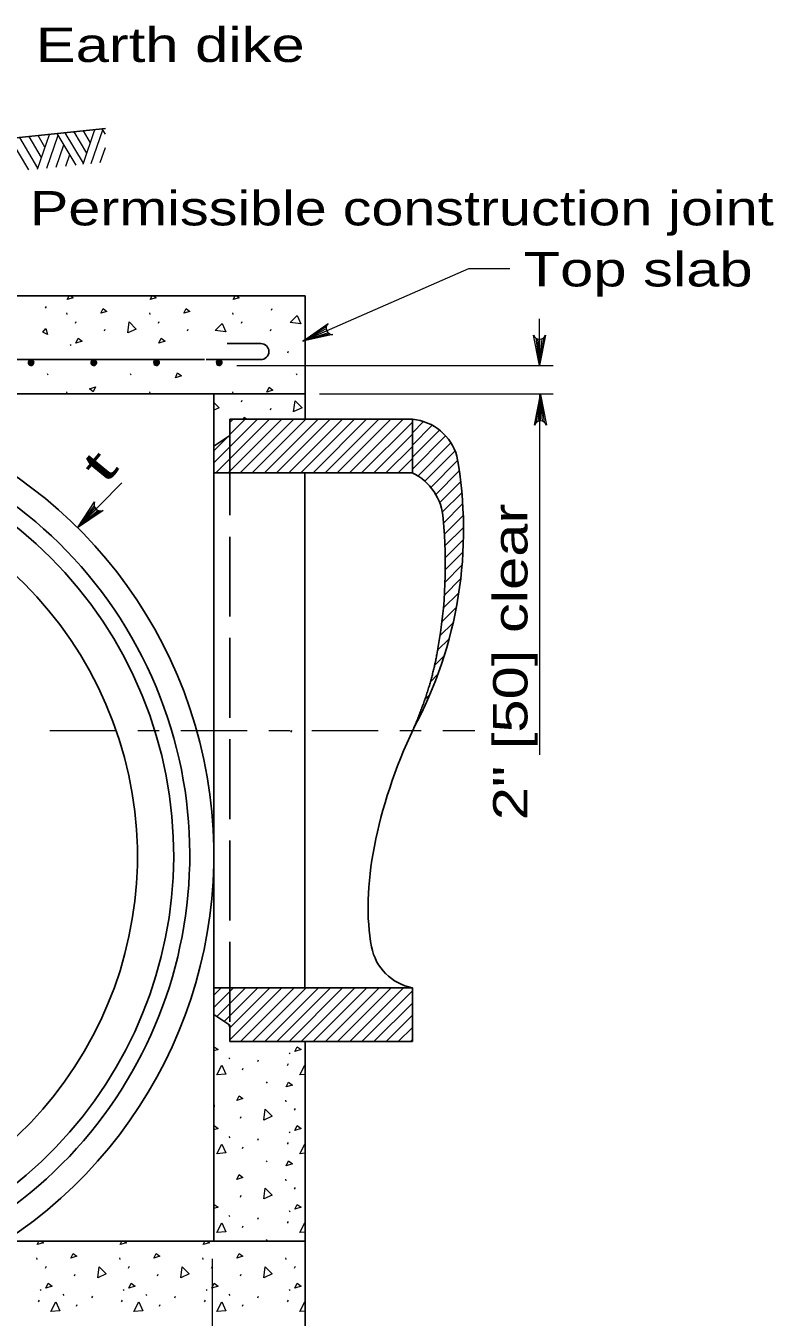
# Model space of a CAD drawing. Extents: x 1073.4 to 1107.4, y 719.4 to 741.4.
# Drawn here: x 1091.11 to 1094.59, y 723.69 to 729.71 of the extents above; entities that cross this region are included whole.
import ezdxf
from ezdxf.enums import TextEntityAlignment as Align

# ---------------------------------------------------------------- set-up
doc = ezdxf.new("R2010")
doc.units = 0
doc.header["$LTSCALE"] = 0.062
doc.linetypes.add('DOT_DASHED', pattern=[7.7, 5, -1.2, 0.3, -1.2])
doc.linetypes.add('LONG_DASHED', pattern=[7.5, 6, -1.5])
doc.layers.add('1', color=7, linetype='Continuous', lineweight=13)

msp = doc.modelspace()

# ---------------------------------------------------------------- linework, layer by layer
at = {"layer": '1', "lineweight": 25}
for p, q in [((1089.772, 729.04842), (1091.48392, 729.22825)), ((1088.59667, 728.44875), (1092.41392, 728.44875)), ((1092.41392, 728.44875), (1092.41392, 727.87408)), ((1092.20792, 728.22683), (1092.05158, 728.22683)), ((1088.59667, 728.15183), (1091.94608, 728.15183)), ((1091.95383, 728.15183), (1092.20792, 728.15183)), ((1092.41392, 727.99275), (1088.59667, 727.99275)), ((1091.98908, 724.04508), (1091.98908, 727.99275)), ((1092.41392, 727.87408), (1092.91367, 727.87408)), ((1092.91367, 727.62417), (1092.91367, 727.87408)), ((1092.91367, 727.62417), (1091.98908, 727.62417)), ((1092.41317, 727.62417), (1092.41317, 725.22558)), ((1092.41392, 724.97575), (1092.41392, 723.54533)), ((1087.26608, 724.04508), (1092.41392, 724.04508))]:
    msp.add_line(p, q, dxfattribs=at)
at = {"layer": '1'}
for p, q in [((1091.12817, 729.03533), (1091.04033, 729.18167)), ((1091.16992, 729.04408), (1091.08475, 729.18642)), ((1091.18675, 729.09408), (1091.12925, 729.19108)), ((1091.16833, 729.0395), (1091.22325, 729.20075)), ((1091.20208, 729.14117), (1091.17025, 729.19533)), ((1091.21092, 729.04408), (1091.26333, 729.19742)), ((1091.34758, 729.05842), (1091.25925, 729.20467)), ((1091.38183, 729.06683), (1091.29692, 729.20858)), ((1091.39783, 729.11342), (1091.33858, 729.213)), ((1091.37992, 729.06175), (1091.435, 729.22358)), ((1091.41442, 729.162), (1091.3815, 729.21742)), ((1091.41825, 729.06583), (1091.47133, 729.22208)), ((1091.48392, 729.20242), (1091.46942, 729.22675)), ((1091.25475, 729.04867), (1091.29017, 729.15325)), ((1091.46025, 729.07025), (1091.48392, 729.14075)), ((1091.29975, 729.05333), (1091.31767, 729.10742)), ((1091.20575, 728.392), (1091.20925, 728.4)), ((1091.30625, 728.43142), (1091.31458, 728.44875)), ((1091.69283, 728.43142), (1091.70117, 728.44875)), ((1092.07942, 728.43142), (1092.08775, 728.44875)), ((1092.1685, 728.44875), (1092.16633, 728.44833)), ((1092.16792, 728.44858), (1092.16675, 728.44875)), ((1091.30283, 728.36942), (1091.30367, 728.36142)), ((1091.68933, 728.36942), (1091.69025, 728.36142)), ((1092.07592, 728.36942), (1092.07683, 728.36142)), ((1092.257, 728.38175), (1092.26058, 728.38975)), ((1093.50608, 728.12433), (1093.50608, 728.34175)), ((1091.34492, 728.32225), (1091.3485, 728.33025)), ((1091.47983, 728.28575), (1091.48342, 728.29375)), ((1091.7315, 728.32225), (1091.73508, 728.33025)), ((1091.86642, 728.28575), (1091.86992, 728.29375)), ((1092.11808, 728.32225), (1092.12158, 728.33025)), ((1092.25292, 728.28575), (1092.25658, 728.29375)), ((1092.51308, 728.30525), (1092.40292, 728.23742)), ((1092.51267, 728.29542), (1092.40292, 728.23742)), ((1092.51508, 728.28658), (1092.40292, 728.23742)), ((1091.31925, 728.22283), (1091.32275, 728.2175)), ((1092.52175, 728.27692), (1092.40292, 728.23742)), ((1092.52958, 728.27133), (1092.40292, 728.23742)), ((1093.48817, 728.2525), (1093.50608, 728.12433)), ((1093.497, 728.24817), (1093.50608, 728.12433)), ((1093.52592, 728.254), (1093.50608, 728.12433)), ((1093.51758, 728.24908), (1093.50608, 728.12433)), ((1093.50608, 728.24683), (1093.50608, 728.12433)), ((1092.33383, 728.18283), (1092.33733, 728.19083)), ((1092.09675, 728.12433), (1093.569, 728.12433)), ((1091.21308, 728.08708), (1091.21658, 728.08175)), ((1091.59967, 728.08708), (1091.60325, 728.08175)), ((1092.37283, 728.08708), (1092.37633, 728.08175)), ((1091.30283, 728.00208), (1091.30367, 727.99408)), ((1091.68933, 728.00208), (1091.69025, 727.99408)), ((1092.07592, 728.00208), (1092.07683, 727.99408)), ((1092.48058, 727.99275), (1093.569, 727.99275)), ((1093.491, 727.859), (1093.51083, 727.98875)), ((1093.49925, 727.86392), (1093.51083, 727.98875)), ((1093.50608, 727.99275), (1093.50608, 726.31108)), ((1093.51083, 727.86617), (1093.51083, 727.98875)), ((1093.51992, 727.86483), (1093.51083, 727.98875)), ((1093.52875, 727.8605), (1093.51083, 727.98875)), ((1092.11808, 727.95492), (1092.12158, 727.96292)), ((1092.25292, 727.9185), (1092.25658, 727.92642)), ((1091.98908, 727.67108), (1092.19208, 727.87408)), ((1091.99875, 727.62417), (1092.24858, 727.87408)), ((1092.05533, 727.62417), (1092.30525, 727.87408)), ((1092.06408, 727.86875), (1092.06933, 727.87408)), ((1092.06408, 727.85908), (1092.07892, 727.87408)), ((1092.06408, 727.80258), (1092.13558, 727.87408)), ((1092.11183, 727.62417), (1092.36167, 727.87408)), ((1092.16842, 727.62417), (1092.41825, 727.87408)), ((1092.22492, 727.62417), (1092.47483, 727.87408)), ((1092.2815, 727.62417), (1092.53133, 727.87408)), ((1092.338, 727.62417), (1092.58792, 727.87408)), ((1092.39458, 727.62417), (1092.64442, 727.87408)), ((1092.45108, 727.62417), (1092.70092, 727.87408)), ((1092.50758, 727.62417), (1092.75758, 727.87408)), ((1092.56417, 727.62417), (1092.814, 727.87408)), ((1092.62075, 727.62417), (1092.87058, 727.87408)), ((1092.67725, 727.62417), (1092.91367, 727.86058)), ((1092.91367, 727.87408), (1092.91492, 727.87408)), ((1092.91367, 727.86708), (1092.91983, 727.87333)), ((1092.91367, 727.8105), (1092.96625, 727.86317)), ((1092.73383, 727.62417), (1092.91367, 727.80408)), ((1092.91367, 727.754), (1093.00558, 727.846)), ((1092.91367, 727.69742), (1093.03992, 727.82375)), ((1091.98908, 727.72758), (1092.05367, 727.79217)), ((1092.79025, 727.62417), (1092.91367, 727.7475)), ((1092.91367, 727.64092), (1093.06892, 727.79617)), ((1092.93892, 727.60975), (1093.09342, 727.76417)), ((1092.84692, 727.62417), (1092.91367, 727.69092)), ((1092.97158, 727.58575), (1093.1125, 727.72667)), ((1092.99925, 727.55683), (1093.12458, 727.68225)), ((1093.02258, 727.52367), (1093.13225, 727.63342)), ((1091.56083, 727.5775), (1091.35433, 727.36875)), ((1093.04075, 727.48533), (1093.13858, 727.58308)), ((1093.05325, 727.44125), (1093.14408, 727.53208)), ((1091.43175, 727.4725), (1091.35433, 727.36875)), ((1091.43492, 727.46317), (1091.35433, 727.36875)), ((1091.4405, 727.45583), (1091.35433, 727.36875)), ((1091.45025, 727.44942), (1091.35433, 727.36875)), ((1091.45958, 727.447), (1091.35433, 727.36875)), ((1093.05875, 727.39033), (1093.14808, 727.4795)), ((1093.0625, 727.3375), (1093.15058, 727.4255)), ((1093.06525, 727.28375), (1093.15183, 727.37017)), ((1093.067, 727.22892), (1093.15158, 727.31342)), ((1093.06683, 727.17217), (1093.14908, 727.25442)), ((1093.06542, 727.11433), (1093.14483, 727.19367)), ((1093.06275, 727.05508), (1093.13858, 727.13092)), ((1093.05775, 726.99358), (1093.13008, 727.06583)), ((1093.051, 726.93017), (1093.11858, 726.99783)), ((1093.04225, 726.865), (1093.10375, 726.92642)), ((1093.03158, 726.79767), (1093.08517, 726.85133)), ((1093.01725, 726.72683), (1093.06192, 726.77158)), ((1092.99783, 726.65083), (1093.03283, 726.68592)), ((1092.97208, 726.56867), (1092.99525, 726.59175)), ((1092.93825, 726.47825), (1092.94683, 726.48683)), ((1092.34733, 726.41708), (1092.35375, 726.42342)), ((1091.98908, 725.19092), (1092.02375, 725.22558)), ((1091.98908, 725.13442), (1092.08025, 725.22558)), ((1092.00275, 725.0915), (1092.13683, 725.22558)), ((1092.03667, 725.06892), (1092.19342, 725.22558)), ((1092.06408, 725.03975), (1092.24992, 725.22558)), ((1092.06408, 724.98317), (1092.3065, 725.22558)), ((1092.11308, 724.97575), (1092.36292, 725.22558)), ((1092.16967, 724.97575), (1092.41958, 725.22558)), ((1092.22617, 724.97575), (1092.47608, 725.22558)), ((1092.28275, 724.97575), (1092.53258, 725.22558)), ((1092.33925, 724.97575), (1092.58917, 725.22558)), ((1092.39583, 724.97575), (1092.64567, 725.22558)), ((1092.45233, 724.97575), (1092.70225, 725.22558)), ((1092.50892, 724.97575), (1092.75883, 725.22558)), ((1092.56542, 724.97575), (1092.81525, 725.22558)), ((1092.622, 724.97575), (1092.87192, 725.22558)), ((1092.6785, 724.97575), (1092.91367, 725.21083)), ((1092.73508, 724.97575), (1092.91367, 725.15425)), ((1092.79158, 724.97575), (1092.91367, 725.09775)), ((1092.84817, 724.97575), (1092.91367, 725.04117)), ((1092.41217, 724.97575), (1092.41392, 724.97392)), ((1092.90475, 724.97575), (1092.91367, 724.98467)), ((1092.33958, 724.9225), (1092.34317, 724.91725)), ((1092.05933, 724.9), (1092.06292, 724.89467)), ((1092.1225, 724.84367), (1092.126, 724.85167)), ((1092.19442, 724.88258), (1092.19792, 724.89058)), ((1092.33292, 724.86408), (1092.33642, 724.87208)), ((1092.41392, 724.82175), (1092.39017, 724.81967)), ((1092.23342, 724.78692), (1092.237, 724.78158)), ((1092.32325, 724.70175), (1092.32408, 724.69375)), ((1092.11358, 724.61825), (1092.11717, 724.62625)), ((1092.36525, 724.65467), (1092.36883, 724.66267)), ((1092.33958, 724.55525), (1092.34317, 724.54992)), ((1092.05933, 724.53267), (1092.06292, 724.52733)), ((1092.19442, 724.51533), (1092.19792, 724.52325)), ((1092.33292, 724.49675), (1092.33642, 724.50475)), ((1092.1225, 724.47633), (1092.126, 724.48433)), ((1092.41392, 724.45442), (1092.39017, 724.45242)), ((1092.23342, 724.41958), (1092.237, 724.41425)), ((1092.32325, 724.33442), (1092.32408, 724.32642)), ((1092.11358, 724.25092), (1092.11717, 724.25892)), ((1092.36525, 724.28733), (1092.36883, 724.29533)), ((1092.05933, 724.16533), (1092.06292, 724.16)), ((1092.19442, 724.148), (1092.19792, 724.15592)), ((1092.33292, 724.12942), (1092.33642, 724.13742)), ((1092.33958, 724.18792), (1092.34317, 724.18258)), ((1092.1225, 724.109), (1092.126, 724.117)), ((1092.41392, 724.08708), (1092.39017, 724.08508)), ((1091.16692, 724.02908), (1091.17458, 724.04508)), ((1091.5535, 724.02908), (1091.56117, 724.04508)), ((1091.94, 724.02908), (1091.94767, 724.04508)), ((1092.23342, 724.05225), (1092.237, 724.04692)), ((1091.16342, 723.96708), (1091.16433, 723.95908)), ((1091.55, 723.96708), (1091.55092, 723.95908)), ((1091.93658, 723.96708), (1091.9375, 723.95908)), ((1091.98275, 722.7255), (1091.98275, 723.96242)), ((1092.32325, 723.96708), (1092.32408, 723.95908)), ((1091.20558, 723.92), (1091.20917, 723.928)), ((1091.3405, 723.88358), (1091.344, 723.89158)), ((1091.59217, 723.92), (1091.59567, 723.928)), ((1091.727, 723.88358), (1091.73058, 723.89158)), ((1091.97867, 723.92), (1091.98225, 723.928)), ((1092.11358, 723.88358), (1092.11717, 723.89158)), ((1092.36525, 723.92), (1092.36883, 723.928)), ((1091.17308, 723.76208), (1091.17667, 723.77008)), ((1091.17983, 723.82058), (1091.18342, 723.81525)), ((1091.28617, 723.798), (1091.28967, 723.79267)), ((1091.42125, 723.78067), (1091.42475, 723.78867)), ((1091.55967, 723.76208), (1091.56325, 723.77008)), ((1091.56642, 723.82058), (1091.56992, 723.81525)), ((1091.67275, 723.798), (1091.67625, 723.79267)), ((1091.80775, 723.78067), (1091.81133, 723.78867)), ((1091.94625, 723.76208), (1091.94983, 723.77008)), ((1091.95292, 723.82058), (1091.95658, 723.81525)), ((1092.05933, 723.798), (1092.06292, 723.79267)), ((1092.19442, 723.78067), (1092.19792, 723.78867)), ((1092.33292, 723.76208), (1092.33642, 723.77008)), ((1092.33958, 723.82058), (1092.34317, 723.81525)), ((1091.34933, 723.74175), (1091.35292, 723.74975)), ((1091.73592, 723.74175), (1091.7395, 723.74975)), ((1092.1225, 723.74175), (1092.126, 723.74975)), ((1092.41392, 723.71975), (1092.39017, 723.71775))]:
    msp.add_line(p, q, dxfattribs=at)
at = {"layer": '1', "linetype": 'LONG_DASHED', "lineweight": 25}
msp.add_line((1092.06408, 727.79908), (1092.06408, 725.05067), dxfattribs=at)
at = {"layer": '1', "linetype": 'DOT_DASHED'}
msp.add_line((1091.225, 726.42483), (1093.20542, 726.42483), dxfattribs=at)
at = {"layer": '1'}
for points in [[(1092.40292, 728.23742), (1093.17758, 728.57675), (1093.36783, 728.57675)], [(1091.32342, 728.44875), (1091.33467, 728.44025), (1091.30625, 728.43142)], [(1091.70992, 728.44875), (1091.72125, 728.44025), (1091.69283, 728.43142)], [(1092.09658, 728.44875), (1092.10783, 728.44025), (1092.07942, 728.43142)], [(1092.39492, 728.31792), (1092.34425, 728.325), (1092.377, 728.35675), (1092.39458, 728.31875)], [(1091.58783, 728.27667), (1091.59492, 728.32742), (1091.62667, 728.2945), (1091.58858, 728.27692)], [(1092.0455, 728.28075), (1091.99475, 728.28775), (1092.02758, 728.31958), (1092.04525, 728.28158)], [(1092.54392, 728.26833), (1092.40292, 728.23742), (1092.52125, 728.32017)], [(1093.53442, 728.26592), (1093.50608, 728.12433), (1093.47775, 728.26592)], [(1093.4825, 727.84708), (1093.51083, 727.98875), (1093.53917, 727.84708)], [(1091.98908, 727.95208), (1092.01325, 727.92717), (1091.98908, 727.91608)], [(1092.36092, 727.90942), (1092.368, 727.96008), (1092.39983, 727.92717), (1092.36175, 727.90967)], [(1092.12575, 727.87408), (1092.1305, 727.88392), (1092.14367, 727.87408)], [(1091.474, 727.4495), (1091.35433, 727.36875), (1091.43375, 727.48933)], [(1092.06408, 725.04475), (1092.06125, 725.0475), (1092.06017, 725.05325)], [(1091.98908, 724.94658), (1091.99117, 724.95092), (1092.00892, 724.93758), (1091.98908, 724.93142)], [(1092.00267, 724.81967), (1092.02667, 724.865), (1092.04525, 724.82325), (1092.00358, 724.81967)], [(1092.38925, 724.81967), (1092.41325, 724.865), (1092.41392, 724.8635)], [(1091.98908, 724.68192), (1091.99117, 724.67975), (1091.98908, 724.65892)], [(1092.22158, 724.60908), (1092.22858, 724.65975), (1092.26042, 724.627), (1092.22242, 724.60933)], [(1091.98908, 724.57925), (1091.99117, 724.58358), (1092.00892, 724.57025), (1091.98908, 724.56408)], [(1092.00267, 724.45242), (1092.02667, 724.49767), (1092.04525, 724.45592), (1092.00358, 724.45242)], [(1092.38925, 724.45242), (1092.41325, 724.49767), (1092.41392, 724.49617)], [(1092.22158, 724.24175), (1092.22858, 724.29242), (1092.26042, 724.25967), (1092.22242, 724.242)], [(1091.98908, 724.212), (1091.99117, 724.21633), (1092.00892, 724.203), (1091.98908, 724.19675)], [(1092.00267, 724.08508), (1092.02667, 724.13033), (1092.04525, 724.08867), (1092.00358, 724.08508)], [(1092.38925, 724.08508), (1092.41325, 724.13033), (1092.41392, 724.12883)], [(1091.18592, 724.04508), (1091.19525, 724.038), (1091.16692, 724.02908)], [(1091.5725, 724.04508), (1091.58192, 724.038), (1091.5535, 724.02908)], [(1091.959, 724.04508), (1091.96842, 724.038), (1091.94, 724.02908)], [(1091.44842, 723.87442), (1091.4555, 723.92508), (1091.48725, 723.89233), (1091.44925, 723.87467)], [(1091.835, 723.87442), (1091.84208, 723.92508), (1091.87392, 723.89233), (1091.83583, 723.87467)], [(1092.22158, 723.87442), (1092.22858, 723.92508), (1092.26042, 723.89233), (1092.22242, 723.87467)], [(1091.2295, 723.71775), (1091.2535, 723.763), (1091.27208, 723.72133), (1091.23033, 723.71775)], [(1091.61608, 723.71775), (1091.64008, 723.763), (1091.65867, 723.72133), (1091.617, 723.71775)], [(1092.00267, 723.71775), (1092.02667, 723.763), (1092.04525, 723.72133), (1092.00358, 723.71775)], [(1092.38925, 723.71775), (1092.41325, 723.763), (1092.41392, 723.7615)]]:
    msp.add_lwpolyline(points, dxfattribs=at)
for points in [[(1091.46225, 728.368), (1091.47292, 728.39008), (1091.49067, 728.37683)], [(1091.84883, 728.368), (1091.8595, 728.39008), (1091.87725, 728.37683)], [(1091.215, 728.26892), (1091.19283, 728.2795), (1091.20617, 728.29725)], [(1091.34667, 728.22908), (1091.35733, 728.25125), (1091.37508, 728.23792)], [(1091.73325, 728.22908), (1091.74392, 728.25125), (1091.76167, 728.23792)], [(1091.80992, 728.0675), (1091.82058, 728.08975), (1091.83833, 728.07642)], [(1091.43825, 728.02442), (1091.42758, 728.00225), (1091.40983, 728.01558)], [(1092.23542, 728.00067), (1092.24608, 728.02283), (1092.26383, 728.0095)], [(1092.367, 724.92875), (1092.37767, 724.95092), (1092.3955, 724.93758)], [(1092.32667, 724.76375), (1092.33733, 724.786), (1092.355, 724.77267)], [(1092.096, 724.70033), (1092.10667, 724.7225), (1092.12442, 724.70917)], [(1092.367, 724.56142), (1092.37767, 724.58358), (1092.3955, 724.57025)], [(1092.32667, 724.39642), (1092.33733, 724.41867), (1092.355, 724.40533)], [(1092.096, 724.33308), (1092.10667, 724.35517), (1092.12442, 724.34183)], [(1092.367, 724.19408), (1092.37767, 724.21633), (1092.3955, 724.203)], [(1091.32292, 723.96575), (1091.33358, 723.98792), (1091.35125, 723.97458)], [(1091.7095, 723.96575), (1091.72008, 723.98792), (1091.73792, 723.97458)], [(1092.096, 723.96575), (1092.10667, 723.98792), (1092.12442, 723.97458)], [(1091.20733, 723.82675), (1091.21792, 723.849), (1091.23567, 723.83567)], [(1091.59392, 723.82675), (1091.60458, 723.849), (1091.62233, 723.83567)], [(1091.9805, 723.82675), (1091.99117, 723.849), (1092.00892, 723.83567)], [(1092.367, 723.82675), (1092.37767, 723.849), (1092.3955, 723.83567)]]:
    msp.add_lwpolyline(points, close=True, dxfattribs=at)
at = {"layer": '1', "lineweight": 25}
for points in [[(1091.98908, 727.74908), (1092.06408, 727.79908), (1092.06408, 727.87408), (1092.41392, 727.87408)], [(1092.41392, 724.97575), (1092.91367, 724.97575), (1092.91367, 725.22558), (1091.98908, 725.22558)], [(1091.98908, 725.10067), (1092.06408, 725.05067), (1092.06408, 724.97575), (1092.41392, 724.97575)]]:
    msp.add_lwpolyline(points, dxfattribs=at)
at = {"layer": '1'}
for centre, start, end in [((1092.54302, 728.29884), 135.74296, 271.56909), ((1093.50605, 728.27734), 202.08782, 337.91395), ((1093.51084, 727.83568), 22.08782, 157.91395), ((1091.46192, 727.47755), 157.39739, 293.22351)]:
    msp.add_arc(centre, 0.03056, start, end, dxfattribs=at)
at = {"layer": '1', "lineweight": 25}
for centre, major_axis, ratio, start_param, end_param in [((1092.20792, 728.18933), (0.03752, 0), 0.999895, 4.712389, 7.8539816), ((1089.84007, 725.84401), (2.03654, 0), 0.999895, 5.2000511, 8.308237), ((1089.8401, 725.84401), (2.14899, 0), 0.999895, 5.291026, 8.8932394), ((1089.8401, 725.84398), (1.96158, 0), 0.999895, 5.1222386, 8.2222672), ((1092.89238, 727.63714), (0.238, 0), 0.999895, 0.2744611, 1.4760278), ((1089.8401, 725.83775), (1.79289, 0), 0.999895, 5.1381757, 8.1439338), ((1091.20122, 727.3573), (1.9509, 0), 0.999895, 5.7890865, 6.4606205), ((1092.80421, 727.39584), (0.25324, 0), 0.999895, 0.0563993, 1.123909), ((1090.83495, 727.19632), (2.23237, 0), 0.999895, 6.1074436, 6.3791106), ((1093.3639, 726.17173), (0.45919, 1.03231), 0.45423, 1.5202582, 2.5699085), ((1092.9581, 725.45936), (-0.238, 0), 0.999895, 0.1813655, 1.3829321)]:
    msp.add_ellipse(centre, major_axis=major_axis, ratio=ratio, start_param=start_param, end_param=end_param, dxfattribs=at)
at = {"layer": '1'}
for centre, major_axis, start_param, end_param in [((1091.13802, 728.13816), (0.01369, 0), 1.8915099, 7.9683372), ((1091.13802, 728.13816), (0.01192, 0), 1.8915085, 7.9683359), ((1091.13802, 728.13816), (0.00893, 0), 1.891505, 7.9683328), ((1091.13802, 728.13816), (0.00724, 0), 1.8915017, 7.9683299), ((1091.13802, 728.13816), (0.00477, 0), 1.8914926, 7.968322), ((1091.13802, 728.13816), (0.00188, 0), 1.8914519, 7.9682863), ((1091.43008, 728.13816), (0.01369, 0), 1.8915099, 7.9683372), ((1091.43008, 728.13816), (0.01192, 0), 1.8915085, 7.9683359), ((1091.43008, 728.13816), (0.00893, 0), 1.891505, 7.9683328), ((1091.43008, 728.13816), (0.00724, 0), 1.8915017, 7.9683299), ((1091.43008, 728.13816), (0.00477, 0), 1.8914926, 7.968322), ((1091.43008, 728.13816), (0.00188, 0), 1.8914519, 7.9682863), ((1091.72215, 728.13816), (0.01369, 0), 1.8915099, 7.9683372), ((1091.72215, 728.13816), (0.01192, 0), 1.8915085, 7.9683359), ((1091.72215, 728.13816), (0.00893, 0), 1.891505, 7.9683328), ((1091.72215, 728.13816), (0.00724, 0), 1.8915017, 7.9683299), ((1091.72215, 728.13816), (0.00477, 0), 1.8914926, 7.968322), ((1091.72215, 728.13816), (0.00188, 0), 1.8914519, 7.9682863), ((1092.01407, 728.13816), (0.01369, 0), 1.8915099, 7.9683372), ((1092.01407, 728.13816), (0.01192, 0), 1.8915085, 7.9683359), ((1092.01407, 728.13816), (0.00893, 0), 1.891505, 7.9683328), ((1092.01407, 728.13816), (0.00724, 0), 1.8915017, 7.9683299), ((1092.01407, 728.13816), (0.00477, 0), 1.8914926, 7.968322), ((1092.01407, 728.13816), (0.00188, 0), 1.8914519, 7.9682863)]:
    msp.add_ellipse(centre, major_axis=major_axis, ratio=0.999895, start_param=start_param, end_param=end_param, dxfattribs=at)
at = {"layer": '1', "lineweight": 25}
msp.add_open_spline([(1092.91875, 726.43217), (1093.00158, 726.62083), (1093.03292, 726.80608)], degree=2, dxfattribs=at)

# ---------------------------------------------------------------- texts
at = {"layer": '1', "width": 1.3}
for s, p in [('Earth dike', (1091.15992, 729.53842)), ('Top slab', (1093.43208, 728.49283))]:
    msp.add_text(s, height=0.16, dxfattribs=at).set_placement(p)
at = {"layer": '1', "width": 1.25}
msp.add_text('Permissible construction joint', height=0.16, dxfattribs=at).set_placement((1092.86462, 728.77717), align=Align.CENTER)
at = {"layer": '1'}
for s, rotation, width, p in [('t', 50.676, 1.75, (1091.48492, 727.56425)), ('2" [50] clear', 90, 1.3, (1093.44983, 726.00617))]:
    msp.add_text(s, height=0.16, rotation=rotation, dxfattribs=dict(at, width=width)).set_placement(p)

doc.saveas('drawing.dxf')
